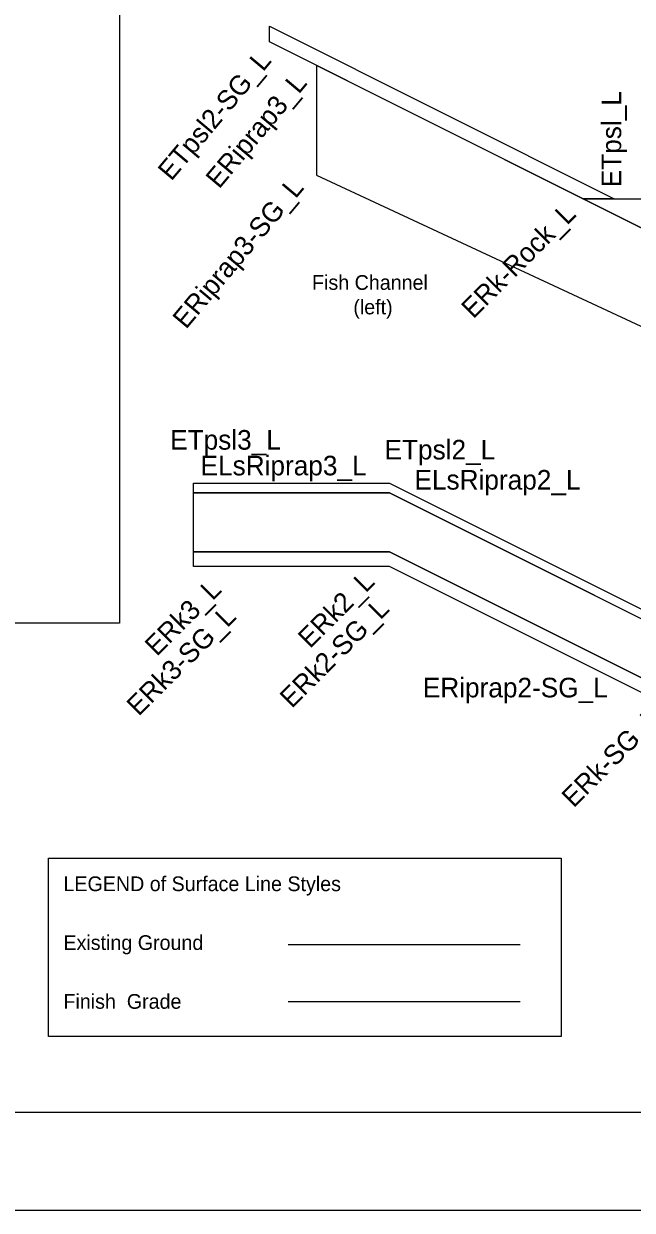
# Model space of a CAD drawing. Extents: x 0 to 1.42, y 0 to 0.92.
# Drawn here: x 0.874 to 1.133, y 0 to 0.504 of the extents above; entities that cross this region are included whole.
import ezdxf

# ---------------------------------------------------------------- set-up
doc = ezdxf.new("R2010")
doc.units = 0
for name, color, linetype in [('#plot_shape', 7, 'Continuous'), ('Default', 7, 'Continuous'), ('Level 63', 7, 'Continuous'), ('P_ODOT_PLAN_Border', 7, 'Continuous'), ('P_RDWY_PLAN_Detail', 7, 'Continuous'), ('P_RDWY_PLAN_DetailTx', 7, 'Continuous')]:
    doc.layers.add(name, color=color, linetype=linetype)

msp = doc.modelspace()

# ---------------------------------------------------------------- linework, layer by layer
at = {"layer": '#plot_shape'}
msp.add_lwpolyline([(0, 0), (1.41667, 0), (1.41667, 0.91667), (0, 0.91667)], close=True, dxfattribs=at)
msp.add_lwpolyline([(0, 0), (1.41667, 0), (1.41667, 0.91667), (0, 0.91667)], close=True, dxfattribs=at)
at = {"layer": 'Level 63'}
for points in [[(0.91493, 0.24948), (0.07445, 0.24948), (0.07445, 0.86481), (0.91493, 0.86481)], [(1.10277, 0.07386), (0.88485, 0.07386), (0.88485, 0.14967), (1.10277, 0.14967)]]:
    msp.add_lwpolyline(points, close=True, dxfattribs=at)
at = {"layer": 'P_ODOT_PLAN_Border'}
msp.add_lwpolyline([(0.0625, 0.04167), (1.39583, 0.04167), (1.39583, 0.875), (0.0625, 0.875)], close=True, dxfattribs=at)
msp.add_lwpolyline([(0.0625, 0.04167), (1.39583, 0.04167), (1.39583, 0.875), (0.0625, 0.875)], close=True, dxfattribs=at)
at = {"layer": 'P_RDWY_PLAN_Detail'}
for p, q in [((0.98675, 0.113), (1.08529, 0.113)), ((0.98675, 0.08877), (1.08529, 0.08877))]:
    msp.add_line(p, q, dxfattribs=at)
for points in [[(0.97872, 0.50327), (1.12539, 0.42994), (1.11205, 0.42994), (0.97872, 0.4966)], [(1.19205, 0.38994), (0.99872, 0.4866), (0.99872, 0.43994), (1.19205, 0.34994), (1.26539, 0.34994), (1.26539, 0.38994)], [(1.26539, 0.4166), (1.26539, 0.38994), (1.19205, 0.38994), (1.11205, 0.42994), (1.21872, 0.42994), (1.23872, 0.4166)], [(1.02986, 0.30908), (1.2132, 0.21741), (1.20487, 0.21741), (1.02986, 0.30491), (0.94653, 0.30491), (0.94653, 0.30908)], [(1.02986, 0.30491), (1.14236, 0.24866), (1.14236, 0.22366), (1.02986, 0.27991), (0.94653, 0.27991), (0.94653, 0.30491)], [(1.02986, 0.27991), (1.14236, 0.22366), (1.14236, 0.21741), (1.02986, 0.27366), (0.94653, 0.27366), (0.94653, 0.27991)]]:
    msp.add_lwpolyline(points, close=True, dxfattribs=at)

# ---------------------------------------------------------------- texts
at = {"layer": 'Default'}
for s, p in [('LEGEND of Surface Line Styles', (0.89117, 0.13564)), ('Existing Ground', (0.89117, 0.11064)), ('Finish  Grade', (0.89117, 0.08564))]:
    msp.add_text(s, height=0.00625, rotation=0, dxfattribs=at).set_placement(p)
at = {"layer": 'P_RDWY_PLAN_Detail'}
for s, p in [('Fish Channel', (0.99687, 0.39121)), ('(left)', (1.01442, 0.38079))]:
    msp.add_text(s, height=0.00625, dxfattribs=at).set_placement(p)
at = {"layer": 'P_RDWY_PLAN_DetailTx'}
for s, rotation, p in [('ETpsl2-SG_L', 50, (0.93702, 0.43714)), ('ERiprap3_L', 50, (0.95736, 0.43379)), ('ETpsl_L', 90, (1.12831, 0.43479)), ('ERiprap3-SG_L', 50, (0.94328, 0.37416)), ('ERk-Rock_L', 45, (1.06541, 0.3786)), ('ERk2_L', 45, (0.996, 0.23844)), ('ERk3_L', 45, (0.93086, 0.23514)), ('ERk2-SG_L', 45, (0.98825, 0.213)), ('ERk3-SG_L', 45, (0.9231, 0.20969)), ('ERk-SG_L', 45, (1.10808, 0.17074))]:
    msp.add_text(s, height=0.00833, rotation=rotation, dxfattribs=at).set_placement(p)
for s, p in [('ETpsl3_L', (0.93654, 0.32328)), ('ETpsl2_L', (1.0277, 0.31911)), ('ELsRiprap3_L', (0.94947, 0.31235)), ('ELsRiprap2_L', (1.04042, 0.30631)), ('ERiprap2-SG_L', (1.04397, 0.21799))]:
    msp.add_text(s, height=0.00833, dxfattribs=at).set_placement(p)

doc.saveas('drawing.dxf')
